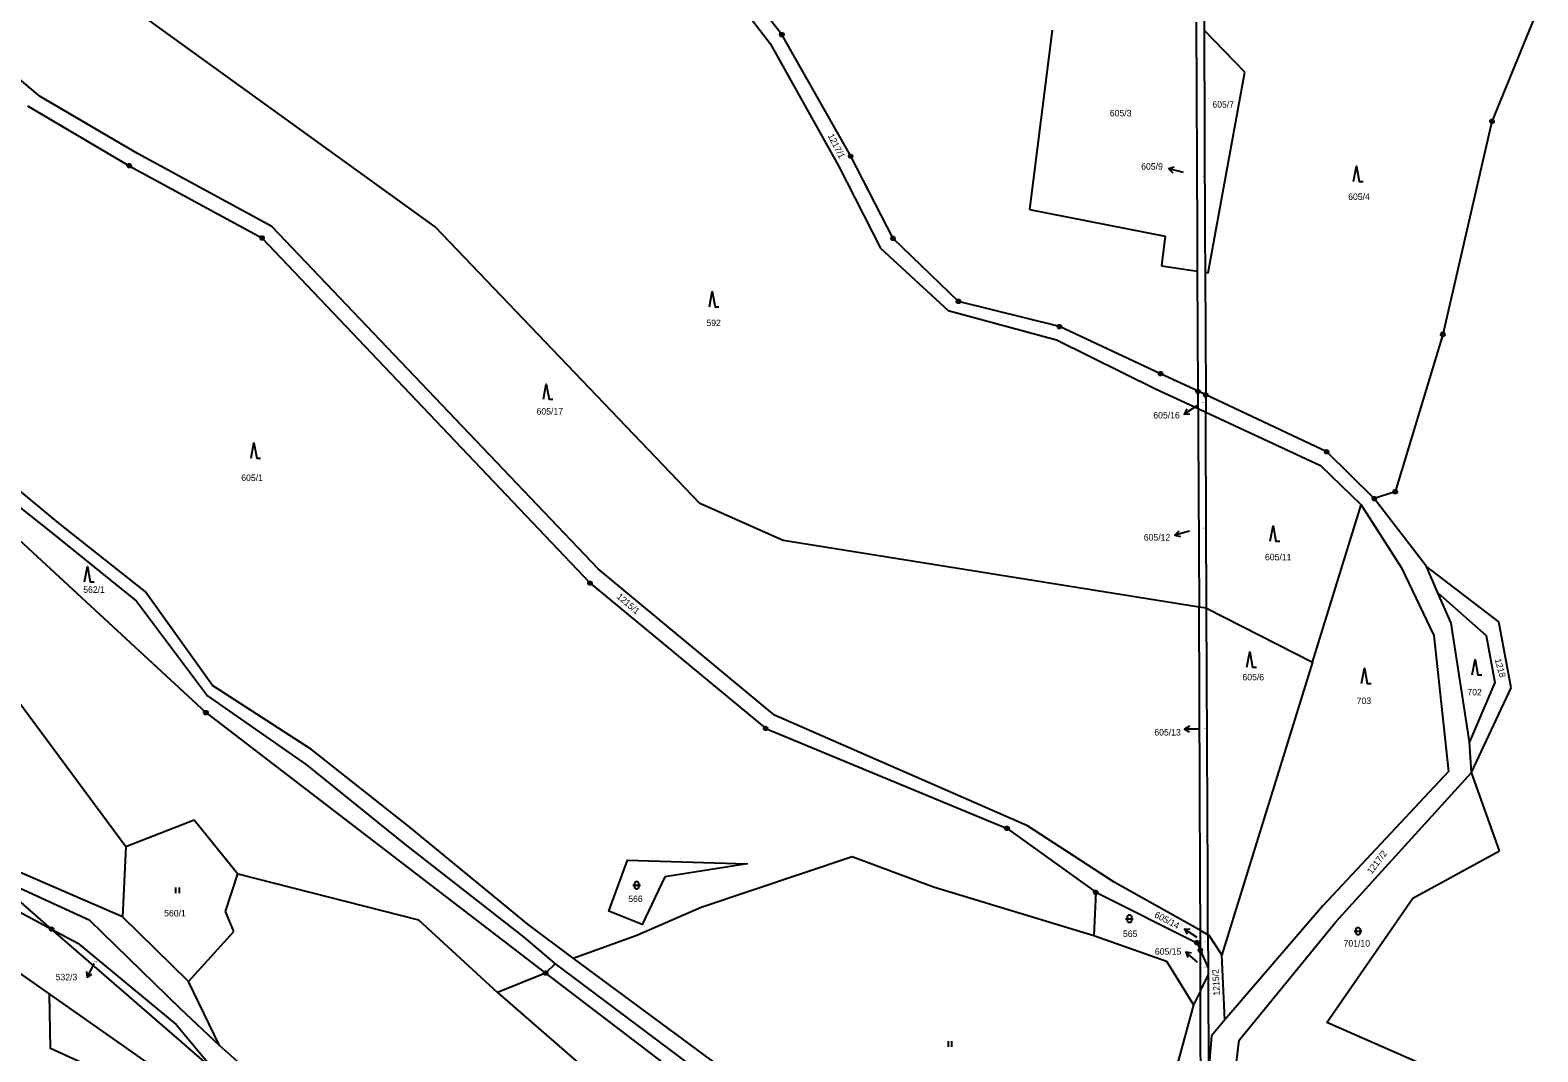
# Model space of a CAD drawing. Extents: x -694465 to -690527, y -983694 to -978978.
# Drawn here: x -692006.8 to -691610.8, y -980544.9 to -980276.6 of the extents above; entities that cross this region are included whole.
import ezdxf

# ---------------------------------------------------------------- set-up
doc = ezdxf.new("R2010")
doc.units = 0
for name, color, linetype in [('Vrstva 1', 7, 'Continuous'), ('Vrstva 16', 7, 'Continuous'), ('Vrstva 18', 7, 'Continuous'), ('Vrstva 24', 7, 'Continuous'), ('Vrstva 25', 7, 'Continuous'), ('Vrstva 29', 7, 'Continuous')]:
    doc.layers.add(name, color=color, linetype=linetype)

msp = doc.modelspace()

# ---------------------------------------------------------------- linework, layer by layer
at = {"layer": 'Vrstva 1'}
for points in [[(-691809.4, -980277.73), (-691826.96, -980255.41)], [(-691698.49, -980266.23), (-691698.45, -980276.57)], [(-691900.49, -980328.25), (-691979.05, -980271.52)], [(-691820.63, -980269.46), (-691812.42, -980280.06)], [(-691610.81, -980271.09), (-691622.88, -980300.54)], [(-691738.38, -980276.56), (-691744.31, -980323.69)], [(-691700.24, -980330.36), (-691700.46, -980274.48)], [(-691698.45, -980276.57), (-691698.24, -980330.36)], [(-691687.81, -980287.64), (-691698.45, -980276.57)], [(-692004.22, -980293.97), (-692024.86, -980276.78)], [(-691812.42, -980280.06), (-691794.54, -980312.22)], [(-691791.28, -980309.66), (-691809.4, -980277.73)], [(-691697.4, -980340.28), (-691687.81, -980287.64)], [(-692007.56, -980296.45), (-691980.81, -980312.18)], [(-691978.65, -980308.95), (-692004.22, -980293.97)], [(-691622.88, -980300.54), (-691635.77, -980356.46)], [(-691980.81, -980312.18), (-691945.96, -980331.14)], [(-691943.33, -980328.16), (-691978.65, -980308.95)], [(-691794.54, -980312.22), (-691783.46, -980333.83)], [(-691780.19, -980331.27), (-691791.28, -980309.66)], [(-691744.31, -980323.69), (-691708.7, -980330.67)], [(-691857.52, -980418.11), (-691943.33, -980328.16)], [(-691830.96, -980400.92), (-691900.49, -980328.25)], [(-691945.96, -980331.14), (-691859.77, -980421.81)], [(-691762.98, -980347.82), (-691780.19, -980331.27)], [(-691708.7, -980330.67), (-691709.69, -980338.48)], [(-691700.2, -980339.88), (-691700.24, -980330.36)], [(-691698.24, -980330.36), (-691698.19, -980340.17)], [(-691783.46, -980333.83), (-691765.68, -980350.23)], [(-691709.69, -980338.48), (-691700.2, -980339.88)], [(-691700.05, -980371.42), (-691700.2, -980339.88)], [(-691698.19, -980340.17), (-691698.04, -980372.37)], [(-691698.19, -980340.17), (-691697.4, -980340.28)], [(-691736.48, -980354.42), (-691762.98, -980347.82)], [(-691765.68, -980350.23), (-691737.21, -980357.93)], [(-691709.89, -980366.79), (-691736.48, -980354.42)], [(-691737.21, -980357.93), (-691711.1, -980370.84)], [(-691635.77, -980356.46), (-691648.28, -980397.8)], [(-691700.05, -980371.42), (-691709.89, -980366.79)], [(-691711.1, -980370.84), (-691700.03, -980375.97)], [(-691698.04, -980372.37), (-691700.05, -980371.42)], [(-691700.03, -980375.97), (-691700.05, -980371.42)], [(-691698.04, -980372.37), (-691698.02, -980376.9)], [(-691666.27, -980387.31), (-691698.04, -980372.37)], [(-691999.78, -980405.72), (-692035.26, -980376.2)], [(-691700.03, -980375.97), (-691700, -980382.04)], [(-691700.03, -980375.97), (-691698.02, -980376.9)], [(-691698, -980382.04), (-691698.02, -980376.9)], [(-691698.02, -980376.9), (-691667.88, -980390.87)], [(-692037.27, -980379.99), (-692001.68, -980408.16)], [(-691700, -980382.04), (-691699.81, -980428.1)], [(-691697.81, -980428.42), (-691698, -980382.04)], [(-691653.76, -980399.59), (-691666.27, -980387.31)], [(-692033.14, -980388.9), (-691960.68, -980455.82)], [(-691667.88, -980390.87), (-691657.24, -980401.27)], [(-691648.28, -980397.8), (-691653.76, -980399.59)], [(-691809.08, -980410.65), (-691830.96, -980400.92)], [(-691670.03, -980442.55), (-691657.24, -980401.27)], [(-691657.24, -980401.27), (-691646.6, -980417.83)], [(-691640.1, -980417.42), (-691653.76, -980399.59)], [(-691976.61, -980424.01), (-691999.78, -980405.72)], [(-692001.68, -980408.16), (-691978.91, -980426.52)], [(-691699.81, -980428.1), (-691809.08, -980410.65)], [(-691811.3, -980456.52), (-691857.52, -980418.11)], [(-691646.6, -980417.83), (-691638.14, -980435.54)], [(-691621.08, -980432.01), (-691640.1, -980417.42)], [(-691637.07, -980424.37), (-691640.1, -980417.42)], [(-691859.77, -980421.81), (-691813.62, -980459.98)], [(-691978.91, -980426.52), (-691960.22, -980451.42)], [(-691958.95, -980448.65), (-691976.61, -980424.01)], [(-691633.58, -980432.29), (-691637.07, -980424.37)], [(-691637.07, -980424.37), (-691624.37, -980435.54)], [(-691697.81, -980428.42), (-691699.81, -980428.1)], [(-691699.51, -980499.27), (-691699.81, -980428.1)], [(-691697.51, -980499.27), (-691697.81, -980428.42)], [(-691697.81, -980428.42), (-691670.03, -980442.55)], [(-691628.8, -980463.51), (-691633.58, -980432.29)], [(-691617.82, -980449.28), (-691621.08, -980432.01)], [(-691638.14, -980435.54), (-691634.27, -980471.3)], [(-691624.37, -980435.54), (-691622.11, -980447.91)], [(-691670.03, -980442.55), (-691684.75, -980490.05)], [(-692016.662, -980443.902), (-691981.74, -980490.99)], [(-691932.94, -980465.48), (-691958.95, -980448.65)], [(-691622.11, -980447.91), (-691628.8, -980463.51)], [(-691628.28, -980471.52), (-691617.82, -980449.28)], [(-691960.22, -980451.42), (-691934.24, -980469.53)], [(-691960.68, -980455.82), (-691871.44, -980524.24)], [(-691744.84, -980485.56), (-691811.3, -980456.52)], [(-691813.62, -980459.98), (-691750.22, -980486.23)], [(-691907.02, -980485.99), (-691932.94, -980465.48)], [(-691628.28, -980471.52), (-691628.8, -980463.51)], [(-691934.24, -980469.53), (-691908.33, -980490.44)], [(-691634.27, -980471.3), (-691667.3, -980506.53)], [(-691663.88, -980510.77), (-691628.28, -980471.52)], [(-691620.85, -980492.08), (-691628.28, -980471.52)], [(-691981.74, -980490.99), (-691963.72, -980483.97)], [(-691963.72, -980483.97), (-691952.3, -980498.15)], [(-691876.02, -980511.5), (-691907.02, -980485.99)], [(-691750.22, -980486.23), (-691726.93, -980503)], [(-691722.14, -980500.31), (-691744.84, -980485.56)], [(-691908.33, -980490.44), (-691877.13, -980514.75)], [(-691684.75, -980490.05), (-691693.86, -980519.44)], [(-691981.74, -980490.99), (-691982.59, -980509.45)], [(-691840.09, -980498.97), (-691846.08, -980511.47), (-691854.8, -980507.99), (-691849.91, -980494.58), (-691818.48, -980495.54), (-691840.09, -980498.97)], [(-691830.6, -980506.94), (-691790.9, -980493.62)], [(-691790.9, -980493.62), (-691769.56, -980501.55)], [(-691643.64, -980504.52), (-691620.85, -980492.08)], [(-692001.19, -980512.68), (-692018.69, -980497.5)], [(-691982.59, -980509.45), (-692010.87, -980497.2)], [(-691955.5, -980508.07), (-691952.3, -980498.15)], [(-691952.3, -980498.15), (-691904.8, -980510.2)], [(-691991.18, -980510.45), (-692013.66, -980500.1)], [(-691769.56, -980501.55), (-691727.44, -980514.35)], [(-691699.46, -980513.04), (-691722.14, -980500.31)], [(-691699.46, -980513.04), (-691699.51, -980499.27)], [(-691697.46, -980514.16), (-691697.51, -980499.27)], [(-692015.06, -980505.27), (-692001.19, -980512.68)], [(-691726.93, -980503), (-691727.44, -980514.35)], [(-691726.93, -980503), (-691700.35, -980516.25)], [(-691666.27, -980537.19), (-691643.64, -980504.52)], [(-691965.23, -980526.48), (-691982.59, -980509.45)], [(-691953.3, -980513.32), (-691955.5, -980508.07)], [(-691904.8, -980510.2), (-691884.05, -980529.31)], [(-691847.51, -980514.23), (-691830.6, -980506.94)], [(-691667.3, -980506.53), (-691692.99, -980536.49)], [(-692025.02, -980513.44), (-692001.777, -980529.752)], [(-691958.42, -980549.84), (-692001.19, -980512.68)], [(-692001.19, -980512.68), (-691994.28, -980516.38)], [(-691967.32, -980533.64), (-691991.18, -980510.45)], [(-691965.23, -980526.48), (-691953.3, -980513.32)], [(-691864.22, -980520.33), (-691876.02, -980511.5)], [(-691864.22, -980520.33), (-691847.51, -980514.23)], [(-691727.44, -980514.35), (-691708.39, -980521.1)], [(-691697.46, -980514.16), (-691699.46, -980513.04)], [(-691699.45, -980518.24), (-691699.46, -980513.04)], [(-691697.18, -980514.32), (-691697.46, -980514.16)], [(-691697.46, -980514.16), (-691697.43, -980522.67)], [(-691693.86, -980519.44), (-691697.18, -980514.32)], [(-691689.28, -980541.86), (-691663.88, -980510.77)], [(-691994.28, -980516.38), (-691968.46, -980537.69)], [(-691877.13, -980514.75), (-691868.9, -980521.82)], [(-691700.35, -980516.25), (-691699.45, -980518.24)], [(-691697.43, -980522.67), (-691699.45, -980518.24)], [(-691699.41, -980528.85), (-691699.45, -980518.24)], [(-691868.9, -980521.82), (-691871.44, -980524.24)], [(-691868.9, -980521.82), (-691812.21, -980564.31)], [(-691810.27, -980560.11), (-691864.22, -980520.33)], [(-691708.39, -980521.1), (-691701.22, -980532.55)], [(-691692.99, -980536.49), (-691693.86, -980519.44)], [(-691871.44, -980524.24), (-691884.05, -980529.31)], [(-691871.44, -980524.24), (-691814.85, -980567.53)], [(-691699.41, -980528.85), (-691697.43, -980524.78)], [(-691697.43, -980522.67), (-691697.43, -980524.78)], [(-691697.43, -980524.78), (-691697.34, -980550.36)], [(-692001.777, -980529.752), (-691960.885, -980558.451)], [(-691961.83, -980559.667), (-691974.647, -980562.961), (-691984.109, -980551.967), (-692001.508, -980544.026), (-692001.777, -980529.752)], [(-691957.06, -980543.23), (-691965.23, -980526.48)], [(-691884.05, -980529.31), (-691853.08, -980556.33)], [(-691699.41, -980528.85), (-691701.22, -980532.55)], [(-691699.3, -980563.72), (-691699.41, -980528.85)], [(-691957.06, -980543.23), (-691967.32, -980533.64)], [(-691701.22, -980532.55), (-691721.15, -980605.51)], [(-691968.46, -980537.69), (-691958.42, -980549.84)], [(-691692.99, -980536.49), (-691696.54, -980540.73)], [(-691638.95, -980549.17), (-691666.27, -980537.19)], [(-691696.54, -980540.73), (-691697.34, -980550.36)], [(-691690.97, -980555.58), (-691689.28, -980541.86)], [(-691952.338, -980547.456), (-691957.06, -980543.23)]]:
    msp.add_lwpolyline(points, dxfattribs=at)
at = {"layer": 'Vrstva 24'}
for points in [[(-691809.246, -980277.254), (-691808.996, -980277.436), (-691808.9, -980277.73), (-691808.996, -980278.024), (-691809.246, -980278.206), (-691809.554, -980278.206), (-691809.804, -980278.024), (-691809.9, -980277.73), (-691809.804, -980277.436), (-691809.554, -980277.254)], [(-691622.726, -980300.064), (-691622.476, -980300.246), (-691622.38, -980300.54), (-691622.476, -980300.834), (-691622.726, -980301.016), (-691623.034, -980301.016), (-691623.284, -980300.834), (-691623.38, -980300.54), (-691623.284, -980300.246), (-691623.034, -980300.064)], [(-691980.656, -980311.704), (-691980.406, -980311.886), (-691980.31, -980312.18), (-691980.406, -980312.474), (-691980.656, -980312.656), (-691980.964, -980312.656), (-691981.214, -980312.474), (-691981.31, -980312.18), (-691981.214, -980311.886), (-691980.964, -980311.704)], [(-691791.126, -980309.184), (-691790.876, -980309.366), (-691790.78, -980309.66), (-691790.876, -980309.954), (-691791.126, -980310.136), (-691791.434, -980310.136), (-691791.684, -980309.954), (-691791.78, -980309.66), (-691791.684, -980309.366), (-691791.434, -980309.184)], [(-691945.806, -980330.664), (-691945.556, -980330.846), (-691945.46, -980331.14), (-691945.556, -980331.434), (-691945.806, -980331.616), (-691946.114, -980331.616), (-691946.364, -980331.434), (-691946.46, -980331.14), (-691946.364, -980330.846), (-691946.114, -980330.664)], [(-691780.036, -980330.794), (-691779.786, -980330.976), (-691779.69, -980331.27), (-691779.786, -980331.564), (-691780.036, -980331.746), (-691780.344, -980331.746), (-691780.594, -980331.564), (-691780.69, -980331.27), (-691780.594, -980330.976), (-691780.344, -980330.794)], [(-691762.826, -980347.344), (-691762.576, -980347.526), (-691762.48, -980347.82), (-691762.576, -980348.114), (-691762.826, -980348.296), (-691763.134, -980348.296), (-691763.384, -980348.114), (-691763.48, -980347.82), (-691763.384, -980347.526), (-691763.134, -980347.344)], [(-691736.326, -980353.944), (-691736.076, -980354.126), (-691735.98, -980354.42), (-691736.076, -980354.714), (-691736.326, -980354.896), (-691736.634, -980354.896), (-691736.884, -980354.714), (-691736.98, -980354.42), (-691736.884, -980354.126), (-691736.634, -980353.944)], [(-691635.616, -980355.984), (-691635.366, -980356.166), (-691635.27, -980356.46), (-691635.366, -980356.754), (-691635.616, -980356.936), (-691635.924, -980356.936), (-691636.174, -980356.754), (-691636.27, -980356.46), (-691636.174, -980356.166), (-691635.924, -980355.984)], [(-691709.736, -980366.314), (-691709.486, -980366.496), (-691709.39, -980366.79), (-691709.486, -980367.084), (-691709.736, -980367.266), (-691710.044, -980367.266), (-691710.294, -980367.084), (-691710.39, -980366.79), (-691710.294, -980366.496), (-691710.044, -980366.314)], [(-691699.896, -980370.944), (-691699.646, -980371.126), (-691699.55, -980371.42), (-691699.646, -980371.714), (-691699.896, -980371.896), (-691700.204, -980371.896), (-691700.454, -980371.714), (-691700.55, -980371.42), (-691700.454, -980371.126), (-691700.204, -980370.944)], [(-691697.886, -980371.894), (-691697.636, -980372.076), (-691697.54, -980372.37), (-691697.636, -980372.664), (-691697.886, -980372.846), (-691698.194, -980372.846), (-691698.444, -980372.664), (-691698.54, -980372.37), (-691698.444, -980372.076), (-691698.194, -980371.894)], [(-691666.116, -980386.834), (-691665.866, -980387.016), (-691665.77, -980387.31), (-691665.866, -980387.604), (-691666.116, -980387.786), (-691666.424, -980387.786), (-691666.674, -980387.604), (-691666.77, -980387.31), (-691666.674, -980387.016), (-691666.424, -980386.834)], [(-691653.606, -980399.114), (-691653.356, -980399.296), (-691653.26, -980399.59), (-691653.356, -980399.884), (-691653.606, -980400.066), (-691653.914, -980400.066), (-691654.164, -980399.884), (-691654.26, -980399.59), (-691654.164, -980399.296), (-691653.914, -980399.114)], [(-691648.126, -980397.324), (-691647.876, -980397.506), (-691647.78, -980397.8), (-691647.876, -980398.094), (-691648.126, -980398.276), (-691648.434, -980398.276), (-691648.684, -980398.094), (-691648.78, -980397.8), (-691648.684, -980397.506), (-691648.434, -980397.324)], [(-691859.616, -980421.334), (-691859.366, -980421.516), (-691859.27, -980421.81), (-691859.366, -980422.104), (-691859.616, -980422.286), (-691859.924, -980422.286), (-691860.174, -980422.104), (-691860.27, -980421.81), (-691860.174, -980421.516), (-691859.924, -980421.334)], [(-691960.526, -980455.344), (-691960.276, -980455.526), (-691960.18, -980455.82), (-691960.276, -980456.114), (-691960.526, -980456.296), (-691960.834, -980456.296), (-691961.084, -980456.114), (-691961.18, -980455.82), (-691961.084, -980455.526), (-691960.834, -980455.344)], [(-691813.466, -980459.504), (-691813.216, -980459.686), (-691813.12, -980459.98), (-691813.216, -980460.274), (-691813.466, -980460.456), (-691813.774, -980460.456), (-691814.024, -980460.274), (-691814.12, -980459.98), (-691814.024, -980459.686), (-691813.774, -980459.504)], [(-691750.066, -980485.754), (-691749.816, -980485.936), (-691749.72, -980486.23), (-691749.816, -980486.524), (-691750.066, -980486.706), (-691750.374, -980486.706), (-691750.624, -980486.524), (-691750.72, -980486.23), (-691750.624, -980485.936), (-691750.374, -980485.754)], [(-691726.776, -980502.524), (-691726.526, -980502.706), (-691726.43, -980503), (-691726.526, -980503.294), (-691726.776, -980503.476), (-691727.084, -980503.476), (-691727.334, -980503.294), (-691727.43, -980503), (-691727.334, -980502.706), (-691727.084, -980502.524)], [(-692001.036, -980512.204), (-692000.786, -980512.386), (-692000.69, -980512.68), (-692000.786, -980512.974), (-692001.036, -980513.156), (-692001.344, -980513.156), (-692001.594, -980512.974), (-692001.69, -980512.68), (-692001.594, -980512.386), (-692001.344, -980512.204)], [(-691700.196, -980515.774), (-691699.946, -980515.956), (-691699.85, -980516.25), (-691699.946, -980516.544), (-691700.196, -980516.726), (-691700.504, -980516.726), (-691700.754, -980516.544), (-691700.85, -980516.25), (-691700.754, -980515.956), (-691700.504, -980515.774)], [(-691699.296, -980517.764), (-691699.046, -980517.946), (-691698.95, -980518.24), (-691699.046, -980518.534), (-691699.296, -980518.716), (-691699.604, -980518.716), (-691699.854, -980518.534), (-691699.95, -980518.24), (-691699.854, -980517.946), (-691699.604, -980517.764)], [(-691871.286, -980523.764), (-691871.036, -980523.946), (-691870.94, -980524.24), (-691871.036, -980524.534), (-691871.286, -980524.716), (-691871.594, -980524.716), (-691871.844, -980524.534), (-691871.94, -980524.24), (-691871.844, -980523.946), (-691871.594, -980523.764)]]:
    msp.add_lwpolyline(points, close=True, dxfattribs=at)
for points in [[(-691809.519, -980277.73), (-691809.28, -980277.73)], [(-691622.999, -980300.54), (-691622.76, -980300.54)], [(-691980.929, -980312.18), (-691980.69, -980312.18)], [(-691791.399, -980309.66), (-691791.16, -980309.66)], [(-691946.079, -980331.14), (-691945.84, -980331.14)], [(-691780.309, -980331.27), (-691780.07, -980331.27)], [(-691763.099, -980347.82), (-691762.86, -980347.82)], [(-691736.599, -980354.42), (-691736.36, -980354.42)], [(-691635.889, -980356.46), (-691635.65, -980356.46)], [(-691710.009, -980366.79), (-691709.77, -980366.79)], [(-691700.169, -980371.42), (-691699.93, -980371.42)], [(-691698.159, -980372.37), (-691697.92, -980372.37)], [(-691666.389, -980387.31), (-691666.15, -980387.31)], [(-691648.399, -980397.8), (-691648.16, -980397.8)], [(-691653.879, -980399.59), (-691653.64, -980399.59)], [(-691859.889, -980421.81), (-691859.65, -980421.81)], [(-691960.799, -980455.82), (-691960.56, -980455.82)], [(-691813.739, -980459.98), (-691813.5, -980459.98)], [(-691750.339, -980486.23), (-691750.1, -980486.23)], [(-691727.049, -980503), (-691726.81, -980503)], [(-692001.309, -980512.68), (-692001.07, -980512.68)], [(-691700.469, -980516.25), (-691700.23, -980516.25)], [(-691699.569, -980518.24), (-691699.33, -980518.24)], [(-691871.559, -980524.24), (-691871.32, -980524.24)]]:
    msp.add_lwpolyline(points, dxfattribs=at)
at = {"layer": 'Vrstva 25'}
for points in [[(-691659.2, -980316.33), (-691658.45, -980312.33), (-691657.7, -980316.33), (-691656.7, -980316.33)], [(-691828.43, -980349.25), (-691827.68, -980345.25), (-691826.93, -980349.25), (-691825.93, -980349.25)], [(-691872.01, -980373.52), (-691871.26, -980369.52), (-691870.51, -980373.52), (-691869.51, -980373.52)], [(-691948.8, -980388.97), (-691948.05, -980384.97), (-691947.3, -980388.97), (-691946.3, -980388.97)], [(-691681.12, -980410.75), (-691680.37, -980406.75), (-691679.62, -980410.75), (-691678.62, -980410.75)], [(-691992.54, -980421.45), (-691991.79, -980417.45), (-691991.04, -980421.45), (-691990.04, -980421.45)], [(-691687.24, -980443.88), (-691686.49, -980439.88), (-691685.74, -980443.88), (-691684.74, -980443.88)], [(-691628.06, -980445.9), (-691627.31, -980441.9), (-691626.56, -980445.9), (-691625.56, -980445.9)], [(-691657.11, -980448.15), (-691656.36, -980444.15), (-691655.61, -980448.15), (-691654.61, -980448.15)], [(-691968.62, -980501.73), (-691968.62, -980503.23)], [(-691967.62, -980503.23), (-691967.62, -980501.73)], [(-691848.51, -980501.17), (-691846.51, -980501.17)], [(-691719.08, -980509.94), (-691717.08, -980509.94)], [(-691659.02, -980513.19), (-691657.02, -980513.19)], [(-691765.72, -980542.13), (-691765.72, -980543.63)], [(-691764.72, -980543.63), (-691764.72, -980542.13)]]:
    msp.add_lwpolyline(points, dxfattribs=at)
for points in [[(-691848.01, -980500.67), (-691847.915, -980500.376), (-691847.665, -980500.194), (-691847.355, -980500.194), (-691847.105, -980500.376), (-691847.01, -980500.67), (-691847.01, -980501.67), (-691847.105, -980501.964), (-691847.355, -980502.146), (-691847.665, -980502.146), (-691847.915, -980501.964), (-691848.01, -980501.67)], [(-691718.58, -980509.44), (-691718.485, -980509.146), (-691718.235, -980508.964), (-691717.925, -980508.964), (-691717.675, -980509.146), (-691717.58, -980509.44), (-691717.58, -980510.44), (-691717.675, -980510.734), (-691717.925, -980510.916), (-691718.235, -980510.916), (-691718.485, -980510.734), (-691718.58, -980510.44)], [(-691658.52, -980512.69), (-691658.425, -980512.396), (-691658.175, -980512.214), (-691657.865, -980512.214), (-691657.615, -980512.396), (-691657.52, -980512.69), (-691657.52, -980513.69), (-691657.615, -980513.984), (-691657.865, -980514.166), (-691658.175, -980514.166), (-691658.425, -980513.984), (-691658.52, -980513.69)]]:
    msp.add_lwpolyline(points, close=True, dxfattribs=at)
at = {"layer": 'Vrstva 29'}
for points in [[(-691706.331, -980312.546), (-691707.776, -980312.951)], [(-691703.9, -980313.94), (-691707.776, -980312.951), (-691706.702, -980313.999)], [(-691700.34, -980375.22), (-691703.694, -980377.399), (-691702.195, -980377.32)], [(-691703.013, -980376.062), (-691703.694, -980377.399)], [(-691705.082, -980408.132), (-691706.155, -980409.18)], [(-691702.28, -980408.19), (-691706.155, -980409.18), (-691704.71, -980409.585)], [(-691702.29, -980459.381), (-691703.59, -980460.131)], [(-691699.59, -980460.13), (-691703.59, -980460.131), (-691702.29, -980460.881)], [(-691700.26, -980514.85), (-691703.637, -980512.706), (-691702.941, -980514.036)], [(-691702.137, -980512.769), (-691703.637, -980512.706)], [(-691990.14, -980521.73), (-691991.882, -980525.331), (-691990.641, -980524.487)], [(-691700.24, -980521.33), (-691703.302, -980518.757), (-691702.79, -980520.167)], [(-691701.825, -980519.019), (-691703.302, -980518.757)], [(-691991.991, -980523.834), (-691991.882, -980525.331)]]:
    msp.add_lwpolyline(points, dxfattribs=at)

# ---------------------------------------------------------------- texts
at = {"layer": 'Vrstva 16'}
for s, p in [('605/9', (-691714.997, -980313.2)), ('605/16', (-691711.82, -980378.56)), ('605/12', (-691714.317, -980410.63)), ('605/13', (-691711.548, -980461.83)), ('605/15', (-691711.407, -980519.4)), ('532/3', (-692000.138, -980526.13))]:
    msp.add_text(s, height=1.7, dxfattribs=at).set_placement(p)
msp.add_text('605/14', height=1.7, rotation=332.08634, dxfattribs=at).set_placement((-691711.668, -980509.435))
at = {"layer": 'Vrstva 18'}
for s, height, p in [('605/7', 1.7, (-691696.303, -980296.93)), ('605/3', 1.7, (-691723.244, -980299.21)), ('605/9', 0.2, (-691699.148, -980315.14)), ('605/4', 1.7, (-691660.633, -980321.16)), ('592', 1.7, (-691829.203, -980354.29)), ('605/17', 1.7, (-691873.823, -980377.54)), ('605/16', 0.2, (-691699.158, -980374.48)), ('605/1', 1.7, (-691951.379, -980394.97)), ('605/12', 0.2, (-691699.038, -980407.37)), ('605/11', 1.7, (-691682.493, -980415.81)), ('562/1', 1.7, (-691992.883, -980424.36)), ('605/6', 1.7, (-691688.403, -980447.34)), ('702', 1.7, (-691629.324, -980451.3)), ('703', 1.7, (-691658.388, -980453.55)), ('605/13', 0.2, (-691698.648, -980460.13)), ('566', 1.7, (-691849.731, -980505.57)), ('560/1', 1.7, (-691971.639, -980509.35)), ('565', 1.7, (-691719.783, -980514.74)), ('605/14', 0.2, (-691698.308, -980516.06)), ('701/10', 1.7, (-691661.84, -980517.26)), ('532/3', 0.2, (-691989.902, -980521.29)), ('605/15', 0.2, (-691698.598, -980522.68))]:
    msp.add_text(s, height=height, dxfattribs=at).set_placement(p)
for s, rotation, p in [('1217/1', 297.02132, (-691797.402, -980304.27)), ('1215/1', 319.48127, (-691852.911, -980425.605)), ('1218', 285.27569, (-691622.148, -980441.871)), ('1217/2', 53.11319, (-691654.464, -980498.396)), ('1215/2', 92.70457, (-691694.349, -980530.108))]:
    msp.add_text(s, height=1.7, rotation=rotation, dxfattribs=at).set_placement(p)

doc.saveas('drawing.dxf')
